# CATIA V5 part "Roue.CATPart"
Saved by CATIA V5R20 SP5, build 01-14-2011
Part number: Roue
Bounding box of the stored display mesh (mm): x -157.972 to 74, y -217.227 to 217.227, z -817.227 to -382.773
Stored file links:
  J:\Thinkmotion\Projet IAO\A envoyer\Roue.CATPart
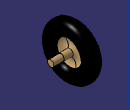
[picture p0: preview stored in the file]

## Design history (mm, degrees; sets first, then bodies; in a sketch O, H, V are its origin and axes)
Body1 (main body)
  Line1: stored without definition
  DatumSurface1
  Line2: stored without definition
  DatumSurface2
  Sketch1 on zx-plane, origin (0, 0, 0), H (-1, 0, 0), V (0, 0, 1)
    point P3 (80, -572.5)
    point P4 (80, -500)
    point P5 (116, -500)
    line L1 (116, -600) -> (-74, -600)
    reference projected line E1 (0, -600) -> (-200, -600) from Line1
    arc A1 centre (35.9591, -536.25) radius 57.0409 from (80, -572.5) to (80, -500) ccw
    point P8 (80, -572.5)
    arc A2 centre (160.0409, -536.25) radius 57.0409 from (116, -500) to (116, -572.5) ccw
    point P10 (116, -572.5)
    line L2 (116, -600) -> (116, -572.5)
    reference intersected line E2 through (0, 0) direction (0, -1) from face of DatumSurface1
    arc A3 centre (98, -442.7636) radius 60 from (116, -500) to (80, -500) ccw
    point P12 (80, -500)
    line L3 (-74, -575) -> (-74, -600)
    line L4 (9, -572.5) -> (9, -572.5)
    point P13 (9, -572.5)
    point P14 (9, -572.5)
    line L5 (9, -572.5) -> (80, -572.5)
    point P15 (80, -572.5)
    reference intersected line E3 through (4, 0) direction (0, -1) from face of DatumSurface2
    line L6 (9, -572.5) -> (9, -575)
    line L7 (9, -575) -> (-74, -575)
    distance A2 A1 = 10
    distance L2 A2 = 13
    distance L2 P3 = 36
    distance P4 E2 = 80
    distance P5 L1 = 100
    distance P4 L1 = 100
    radius A3 = 60
    length L5 = 71
    distance L4 E3 = 5
    distance L5 L1 = 27.5
    distance L7 L1 = 25
    distance L6 L3 = 83
    horizontal: L1 H, L5 H, L7 H
    coincidence: L1 E1, P5 L2, P12 A1, P12 P4, P3 P15, P8 P3, P10 L5, P13 P14
    vertical: L2 V, L3 V, L4 V, L6 V
  Shaft1: profile Sketch1, axis Line2, angle 360
  Chamfer1: length 1, angle 45, on face of Shaft1 from Sketch1.L3
  Sketch2 on zx-plane, origin (0, 0, 0), H (-1, 0, 0), V (0, 0, 1)
    point P3 (80, -572.5)
    point P4 (80, -500)
    point P5 (116, -500)
    line L1 (116, -600) -> (-74, -600)
    reference projected line E1 (0, -600) -> (-200, -600) from Line1
    arc A1 centre (35.9591, -536.25) radius 57.0409 from (80, -572.5) to (80, -500) ccw
    point P8 (80, -572.5)
    arc A2 centre (160.0409, -536.25) radius 57.0409 from (116, -500) to (116, -572.5) ccw
    point P10 (116, -572.5)
    line L2 (116, -600) -> (116, -572.5)
    reference intersected line E2 through (0, 0) direction (0, -1) from face of DatumSurface1
    arc A3 centre (98, -442.7636) radius 60 from (116, -500) to (80, -500) ccw
    point P12 (80, -500)
    line L3 (-74, -575) -> (-74, -600)
    line L4 (9, -572.5) -> (9, -572.5)
    point P13 (9, -572.5)
    point P14 (9, -572.5)
    line L5 (9, -572.5) -> (80, -572.5)
    point P15 (80, -572.5)
    reference intersected line E3 through (4, 0) direction (0, -1) from face of DatumSurface2
    line L6 (9, -572.5) -> (9, -575)
    line L7 (9, -575) -> (-74, -575)
    distance A2 A1 = 10
    distance L2 A2 = 13
    distance L2 P3 = 36
    distance P4 E2 = 80
    distance P5 L1 = 100
    distance P4 L1 = 100
    radius A3 = 60
    length L5 = 71
    distance L4 E3 = 5
    distance L5 L1 = 27.5
    distance L7 L1 = 25
    distance L6 L3 = 83
    horizontal: L1 H, L5 H, L7 H
    coincidence: L1 E1, P5 L2, P12 A1, P12 P4, P3 P15, P8 P3, P10 L5, P13 P14
    vertical: L2 V, L3 V, L4 V, L6 V
  Shaft2: profile Sketch2, axis Line2, angle 360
